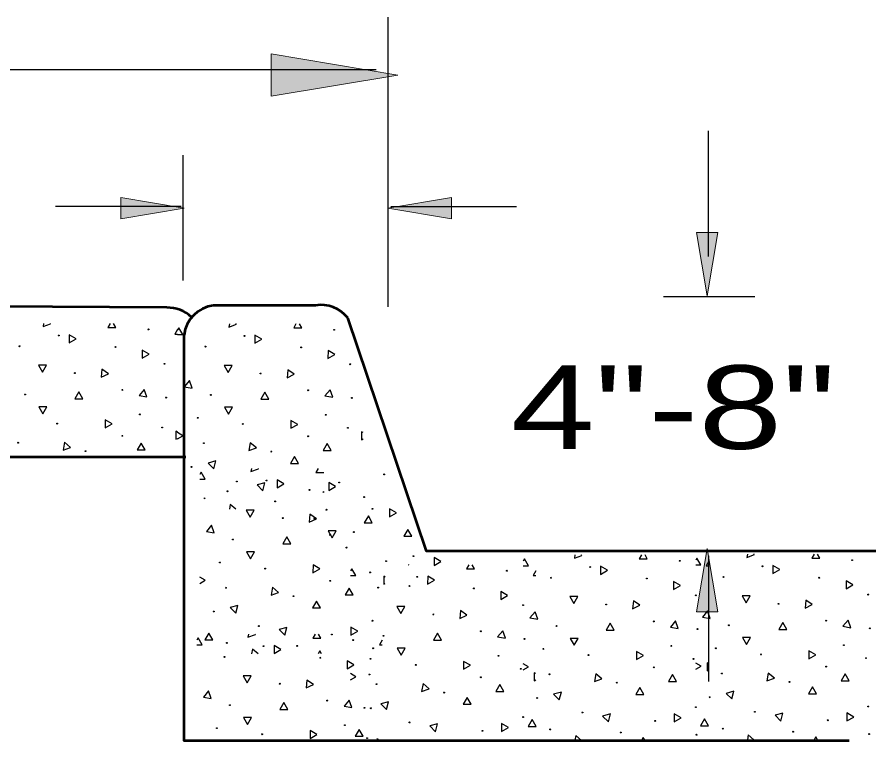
# Model space of a CAD drawing. Extents: x 75.6 to 110.9, y 28 to 50.
# Drawn here: x 101.892 to 103.142, y 35.919 to 36.973 of the extents above; entities that cross this region are included whole.
import ezdxf
from ezdxf.enums import TextEntityAlignment as Align

# ---------------------------------------------------------------- set-up
doc = ezdxf.new("R2010")
doc.units = 0
doc.header["$LTSCALE"] = 0.06
doc.layers.add('1', color=7, linetype='Continuous', lineweight=25)
doc.layers.add('3', color=7, linetype='Continuous', lineweight=13)

msp = doc.modelspace()

# ---------------------------------------------------------------- hatches: boundary and pattern name
at = {"layer": '3'}
for points in [[(102.26167, 36.9195), (102.26167, 36.85792), (102.44625, 36.88875), (102.44625, 36.88875)], [(102.04292, 36.6795), (102.04292, 36.71025), (102.13525, 36.69483), (102.13525, 36.69483)], [(102.52425, 36.6795), (102.52425, 36.71025), (102.43192, 36.69483), (102.43192, 36.69483)], [(102.912, 36.65958), (102.88125, 36.65958), (102.89667, 36.56733), (102.89667, 36.56733)], [(102.912, 36.10692), (102.88125, 36.10692), (102.89667, 36.19925), (102.89667, 36.19925)]]:
    msp.add_hatch(color=256, dxfattribs=at).paths.add_polyline_path(points)

# ---------------------------------------------------------------- linework, layer by layer
at = {"layer": '1', "lineweight": 53}
for p, q in [((102.10992, 36.55025), (98.82217, 36.57225)), ((102.32642, 36.55342), (102.17775, 36.55342)), ((102.13775, 36.33233), (98.82217, 36.33233))]:
    msp.add_line(p, q, dxfattribs=at)
at = {"layer": '1'}
for p, q in [((101.93058, 36.527), (101.92983, 36.52242)), ((101.92983, 36.52242), (101.94075, 36.52642)), ((101.94075, 36.52642), (101.94, 36.527)), ((102.02758, 36.527), (102.02425, 36.52125)), ((102.03592, 36.52125), (102.03258, 36.527)), ((102.201, 36.52642), (102.20025, 36.52183)), ((102.20025, 36.52183), (102.21117, 36.52583)), ((102.21117, 36.52583), (102.21042, 36.52642)), ((102.298, 36.52642), (102.29467, 36.52067)), ((102.30633, 36.52067), (102.303, 36.52642)), ((102.02425, 36.52125), (102.03592, 36.52125)), ((102.12533, 36.51817), (102.12142, 36.51133)), ((102.12767, 36.52083), (102.12575, 36.51758)), ((102.13342, 36.51075), (102.12767, 36.52083)), ((102.29467, 36.52067), (102.30633, 36.52067)), ((102.12142, 36.51133), (102.12533, 36.51133)), ((102.12575, 36.51075), (102.13342, 36.51075)), ((102.123, 36.37), (102.123, 36.35833)), ((102.123, 36.37), (102.123, 36.35833)), ((102.12533, 36.36867), (102.123, 36.37)), ((102.12533, 36.36867), (102.123, 36.37)), ((102.39342, 36.36942), (102.39342, 36.35775)), ((102.39342, 36.36942), (102.39342, 36.35775)), ((102.39575, 36.36808), (102.39342, 36.36942)), ((102.39575, 36.36808), (102.39342, 36.36942)), ((102.123, 36.35833), (102.12533, 36.35967)), ((102.123, 36.35833), (102.12533, 36.35967)), ((102.39342, 36.35775), (102.39575, 36.35908)), ((102.39342, 36.35775), (102.39575, 36.35908)), ((102.23325, 36.31583), (102.23242, 36.31125)), ((102.23242, 36.31125), (102.24342, 36.31525)), ((102.24342, 36.31525), (102.24275, 36.31583)), ((102.33025, 36.31583), (102.32692, 36.31008)), ((102.15992, 36.31025), (102.158, 36.307)), ((102.158, 36.30025), (102.16575, 36.30025)), ((102.16575, 36.30025), (102.15992, 36.31025)), ((102.32692, 36.31008), (102.3385, 36.31008)), ((102.70408, 36.18992), (102.70333, 36.18533)), ((102.70333, 36.18533), (102.71425, 36.18933)), ((102.71425, 36.18933), (102.7135, 36.18992)), ((102.80108, 36.18992), (102.79775, 36.18417)), ((102.80942, 36.18417), (102.80608, 36.18992)), ((102.95508, 36.19092), (102.95433, 36.18642)), ((102.95433, 36.18642), (102.96533, 36.19042)), ((102.96533, 36.19042), (102.96458, 36.19092)), ((103.05208, 36.19092), (103.04875, 36.18525)), ((103.06042, 36.18525), (103.05708, 36.19092)), ((102.46267, 36.17492), (102.46192, 36.1755)), ((102.5495, 36.1755), (102.54608, 36.16975)), ((102.55775, 36.16975), (102.55442, 36.1755)), ((102.63075, 36.18433), (102.62883, 36.18108)), ((102.62883, 36.17425), (102.6365, 36.17425)), ((102.6365, 36.17425), (102.63075, 36.18433)), ((102.79775, 36.18417), (102.80942, 36.18417)), ((102.88175, 36.18542), (102.87992, 36.18217)), ((102.87992, 36.17533), (102.88758, 36.17533)), ((102.88758, 36.17533), (102.88175, 36.18542)), ((102.89883, 36.18108), (102.89492, 36.17425)), ((102.89492, 36.17425), (102.89883, 36.17425)), ((103.04875, 36.18525), (103.06042, 36.18525)), ((102.37908, 36.16992), (102.37725, 36.16667)), ((102.38492, 36.15992), (102.37908, 36.16992)), ((102.54608, 36.16975), (102.55775, 36.16975)), ((102.64725, 36.16667), (102.64333, 36.15992)), ((102.37725, 36.15992), (102.38492, 36.15992)), ((102.42575, 36.15883), (102.42567, 36.14725)), ((102.42575, 36.15883), (102.42567, 36.14725)), ((102.428, 36.1575), (102.42575, 36.15883)), ((102.428, 36.1575), (102.42575, 36.15883)), ((102.64333, 36.15992), (102.64725, 36.15992)), ((102.42567, 36.14725), (102.428, 36.14858)), ((102.42567, 36.14725), (102.428, 36.14858)), ((102.22883, 36.07458), (102.22808, 36.07)), ((102.22808, 36.07), (102.239, 36.074)), ((102.239, 36.074), (102.23833, 36.07458)), ((102.32583, 36.07458), (102.3225, 36.06883)), ((102.33408, 36.06883), (102.33075, 36.07458)), ((102.1555, 36.069), (102.15358, 36.06575)), ((102.16133, 36.05892), (102.1555, 36.069)), ((102.3225, 36.06883), (102.33408, 36.06883)), ((102.42358, 36.06575), (102.41967, 36.05892)), ((102.15358, 36.05892), (102.16133, 36.05892)), ((102.41967, 36.05892), (102.42358, 36.05892)), ((102.8965, 36.03292), (102.8965, 36.02125)), ((102.8965, 36.03292), (102.8965, 36.02125)), ((102.89883, 36.03158), (102.8965, 36.03292)), ((102.89883, 36.03158), (102.8965, 36.03292)), ((102.64492, 36.0185), (102.64492, 36.00683)), ((102.64492, 36.0185), (102.64492, 36.00683)), ((102.64725, 36.01717), (102.64492, 36.0185)), ((102.64725, 36.01717), (102.64492, 36.0185)), ((102.8965, 36.02125), (102.89883, 36.02258)), ((102.8965, 36.02125), (102.89883, 36.02258)), ((102.64492, 36.00683), (102.64725, 36.00825)), ((102.64492, 36.00683), (102.64725, 36.00825))]:
    msp.add_line(p, q, dxfattribs=at)
at = {"layer": '1', "lineweight": 53}
for points in [[(103.14208, 36.19567), (102.48817, 36.19567), (102.37333, 36.53525)], [(103.10308, 35.91925), (102.13525, 35.91925), (102.13525, 36.51258)]]:
    msp.add_lwpolyline(points, dxfattribs=at)
at = {"layer": '1'}
for points in [[(101.96775, 36.49875), (101.97783, 36.50467), (101.96783, 36.5105)], [(102.23817, 36.49817), (102.24825, 36.50408), (102.23825, 36.50992)], [(102.07408, 36.4765), (102.08425, 36.48233), (102.07425, 36.48817)], [(102.3445, 36.47592), (102.35467, 36.48175), (102.34467, 36.48758)], [(101.92883, 36.45633), (101.93458, 36.46633), (101.923, 36.46633)], [(102.19925, 36.45575), (102.205, 36.46575), (102.19342, 36.46575)], [(102.0145, 36.44867), (102.025, 36.45367), (102.01558, 36.46033)], [(102.28492, 36.44808), (102.29542, 36.45308), (102.286, 36.45975)], [(102.13542, 36.43492), (102.14692, 36.43292), (102.143, 36.44375)], [(101.97625, 36.41742), (101.98783, 36.41742), (101.982, 36.4275)], [(102.06958, 36.42208), (102.08108, 36.42008), (102.07717, 36.431)], [(102.24667, 36.41683), (102.25825, 36.41683), (102.25242, 36.42692)], [(102.34, 36.4215), (102.3515, 36.4195), (102.34758, 36.43042)], [(101.92925, 36.39542), (101.93508, 36.4055), (101.92342, 36.4055)], [(102.19967, 36.39483), (102.2055, 36.40492), (102.19383, 36.40492)], [(102.02017, 36.37492), (102.03025, 36.38067), (102.02025, 36.3865)], [(102.29058, 36.37433), (102.30067, 36.38008), (102.29067, 36.38592)], [(101.959, 36.3425), (101.96992, 36.3465), (101.961, 36.354)], [(102.06692, 36.34283), (102.07858, 36.34283), (102.07275, 36.35292)], [(102.22942, 36.34192), (102.24033, 36.34592), (102.23142, 36.35342)], [(102.33733, 36.34225), (102.349, 36.34225), (102.34317, 36.35233)], [(102.17825, 36.31558), (102.18125, 36.32683), (102.17, 36.32383)], [(102.28983, 36.32333), (102.30142, 36.32333), (102.29567, 36.33342)], [(102.27042, 36.28758), (102.2805, 36.2935), (102.27042, 36.29933)], [(102.24967, 36.2835), (102.25267, 36.29483), (102.24133, 36.29183)], [(102.34567, 36.28358), (102.35567, 36.28942), (102.34567, 36.29525)], [(102.23142, 36.24517), (102.23733, 36.25525), (102.22567, 36.25525)], [(102.31708, 36.23758), (102.32775, 36.2425), (102.31817, 36.24917)], [(102.43425, 36.24558), (102.44433, 36.25142), (102.43433, 36.25725)], [(102.39742, 36.23683), (102.40908, 36.23683), (102.40333, 36.24692)], [(102.16775, 36.22433), (102.17908, 36.22233), (102.17517, 36.23325)], [(102.3505, 36.21483), (102.35633, 36.22492), (102.34475, 36.22492)], [(102.45492, 36.21708), (102.46658, 36.21708), (102.46075, 36.22717)], [(102.27883, 36.20625), (102.2905, 36.20625), (102.28475, 36.21633)], [(102.23192, 36.18425), (102.23775, 36.19442), (102.22608, 36.19442)], [(102.32275, 36.16375), (102.33292, 36.16958), (102.32283, 36.17542)], [(102.49892, 36.17458), (102.509, 36.18042), (102.49892, 36.18625)], [(102.99233, 36.16275), (103.00242, 36.16858), (102.99233, 36.17442)], [(102.74125, 36.16167), (102.75133, 36.16758), (102.74133, 36.17342)], [(102.48967, 36.14725), (102.49975, 36.15317), (102.48975, 36.159)], [(102.84758, 36.13942), (102.85775, 36.14525), (102.84775, 36.15108)], [(103.09867, 36.14042), (103.10875, 36.14625), (103.09875, 36.15217)], [(102.26167, 36.13142), (102.27258, 36.13542), (102.26375, 36.14283)], [(102.3695, 36.13167), (102.38117, 36.13167), (102.37542, 36.14175)], [(102.596, 36.125), (102.60608, 36.13083), (102.59608, 36.13667)], [(102.70233, 36.11925), (102.70808, 36.12925), (102.6965, 36.12925)], [(102.95333, 36.12025), (102.95917, 36.13033), (102.9475, 36.13033)], [(103.03908, 36.11267), (103.04958, 36.11758), (103.04008, 36.12425)], [(102.2105, 36.105), (102.2135, 36.11625), (102.20225, 36.11325)], [(102.32208, 36.11283), (102.33375, 36.11283), (102.32792, 36.12283)], [(102.45075, 36.10483), (102.4565, 36.11492), (102.44492, 36.11492)], [(102.788, 36.11158), (102.7985, 36.11658), (102.78908, 36.12325)], [(102.53642, 36.09725), (102.54692, 36.10217), (102.53742, 36.10883)], [(102.6385, 36.09842), (102.65, 36.09642), (102.64608, 36.10725)], [(102.88958, 36.09942), (102.90108, 36.09742), (102.89708, 36.10833)], [(102.74975, 36.08033), (102.76133, 36.08033), (102.7555, 36.09042)], [(102.84308, 36.085), (102.85458, 36.083), (102.85067, 36.09392)], [(103.00075, 36.08142), (103.01242, 36.08142), (103.00658, 36.09142)], [(103.09417, 36.086), (103.10567, 36.084), (103.10175, 36.095)], [(102.16508, 36.06625), (102.17675, 36.06625), (102.17092, 36.07625)], [(102.28183, 36.073), (102.28483, 36.08425), (102.27358, 36.08125)], [(102.37783, 36.073), (102.38792, 36.07883), (102.37792, 36.08467)], [(102.49808, 36.06592), (102.50975, 36.06592), (102.50392, 36.076)], [(102.5915, 36.07058), (102.603, 36.06858), (102.59908, 36.07958)], [(102.70275, 36.05833), (102.70858, 36.06842), (102.69692, 36.06842)], [(102.95375, 36.05942), (102.95967, 36.0695), (102.948, 36.0695)], [(102.266, 36.04633), (102.27608, 36.05225), (102.26608, 36.058)], [(102.45108, 36.04392), (102.457, 36.054), (102.44533, 36.054)], [(102.79367, 36.03783), (102.80375, 36.04358), (102.79375, 36.04942)], [(103.04475, 36.03883), (103.05475, 36.04467), (103.04475, 36.0505)], [(102.37233, 36.024), (102.38242, 36.02992), (102.37242, 36.03575)], [(102.54208, 36.02342), (102.55208, 36.02925), (102.54208, 36.035)], [(102.22708, 36.00383), (102.23292, 36.01392), (102.22125, 36.01392)], [(102.7325, 36.00542), (102.74342, 36.00942), (102.7345, 36.01692)], [(102.84042, 36.00575), (102.85208, 36.00575), (102.84625, 36.01583)], [(102.9835, 36.0065), (102.9945, 36.0105), (102.98558, 36.01792)], [(103.09142, 36.00683), (103.10308, 36.00683), (103.09733, 36.01683)], [(102.31275, 35.99625), (102.32333, 36.00125), (102.31375, 36.00783)], [(102.48092, 35.991), (102.49183, 35.995), (102.48292, 36.0025)], [(102.58875, 35.99133), (102.60042, 35.99133), (102.59467, 36.00142)], [(102.16333, 35.983), (102.17475, 35.981), (102.17075, 35.99192)], [(102.68133, 35.97908), (102.68433, 35.99033), (102.67308, 35.98733)], [(102.79292, 35.98683), (102.8045, 35.98683), (102.79875, 35.99692)], [(102.93242, 35.98017), (102.93542, 35.99142), (102.92408, 35.98842)], [(103.04392, 35.98792), (103.05558, 35.98792), (103.04975, 35.99792)], [(102.27442, 35.965), (102.28608, 35.965), (102.28033, 35.975)], [(102.36792, 35.96958), (102.37933, 35.96758), (102.37542, 35.97858)], [(102.42975, 35.96467), (102.43275, 35.97592), (102.4215, 35.97292)], [(102.54133, 35.97242), (102.55292, 35.97242), (102.54708, 35.9825)], [(102.2275, 35.943), (102.23333, 35.95308), (102.22175, 35.95308)], [(102.63592, 35.94025), (102.64758, 35.94025), (102.64175, 35.95033)], [(102.75275, 35.947), (102.75575, 35.95833), (102.74442, 35.95533)], [(102.84875, 35.94708), (102.85875, 35.95292), (102.84875, 35.95875)], [(102.887, 35.94133), (102.89867, 35.94133), (102.89283, 35.95142)], [(103.00375, 35.94808), (103.00675, 35.95942), (102.9955, 35.95642)], [(103.09975, 35.94817), (103.10983, 35.95392), (103.09975, 35.95983)], [(102.50108, 35.93258), (102.50408, 35.94392), (102.49283, 35.94092)], [(102.59708, 35.93267), (102.60717, 35.9385), (102.59708, 35.94433)], [(102.31842, 35.92242), (102.3285, 35.92825), (102.31842, 35.93408)], [(102.38433, 35.92592), (102.396, 35.92592), (102.39017, 35.93592)]]:
    msp.add_lwpolyline(points, close=True, dxfattribs=at)
for points in [[(102.12575, 36.35908), (102.1335, 36.36358), (102.12575, 36.36808)], [(102.21042, 36.25642), (102.20225, 36.26333), (102.201, 36.25642)], [(102.21042, 36.25642), (102.20225, 36.26333), (102.201, 36.25642)], [(102.158, 36.14858), (102.16575, 36.153), (102.158, 36.1575)], [(102.24275, 36.04583), (102.2345, 36.05275), (102.23325, 36.04583)], [(102.24275, 36.04583), (102.2345, 36.05275), (102.23325, 36.04583)], [(102.33517, 36.04583), (102.33275, 36.05017), (102.33025, 36.04583)], [(102.62883, 36.02258), (102.63658, 36.02708), (102.62883, 36.03158)], [(102.87992, 36.02358), (102.88767, 36.02817), (102.87992, 36.03258)], [(102.37725, 36.00825), (102.385, 36.01267), (102.37725, 36.01717)], [(102.7135, 35.91992), (102.70533, 35.92683), (102.70408, 35.91992)], [(102.7135, 35.91992), (102.70533, 35.92683), (102.70408, 35.91992)], [(102.80608, 35.91992), (102.80358, 35.92425), (102.80108, 35.91992)], [(102.96458, 35.92092), (102.95642, 35.92783), (102.95508, 35.92092)], [(102.96458, 35.92092), (102.95642, 35.92783), (102.95508, 35.92092)], [(103.05708, 35.92092), (103.05467, 35.92525), (103.05208, 35.92092)]]:
    msp.add_lwpolyline(points, dxfattribs=at)
for centre in [(102.08315, 36.51842), (102.35356, 36.51783), (101.95262, 36.50948), (102.22304, 36.5089), (101.89572, 36.49387), (102.03518, 36.49277), (102.16614, 36.49329), (102.30559, 36.49218), (102.10659, 36.46822), (102.37701, 36.46764), (101.97605, 36.45483), (102.24646, 36.45425), (101.90355, 36.42358), (102.04523, 36.43028), (102.31565, 36.4297), (102.10882, 36.41912), (102.17397, 36.423), (102.37923, 36.41854), (102.07088, 36.39458), (102.155, 36.38954), (102.3413, 36.39399), (101.9504, 36.38119), (102.10324, 36.37561), (102.22081, 36.38061), (102.37365, 36.37503), (102.04523, 36.36335), (102.31565, 36.36276), (101.89349, 36.35331), (102.16391, 36.35273), (101.99168, 36.34103), (102.2621, 36.34044), (102.14607, 36.31815), (102.25527, 36.29835), (102.4264, 36.3073), (102.21188, 36.29693), (102.36093, 36.2954), (102.19837, 36.28274), (102.31788, 36.28467), (102.33783, 36.28163), (102.3973, 36.27425), (102.16503, 36.2724), (102.26768, 36.26793), (102.34233, 36.25585), (102.40924, 36.25709), (102.2787, 36.2437), (102.3248, 36.243), (102.3823, 36.22325), (102.2062, 36.21245), (102.34788, 36.21915), (102.37165, 36.20061), (102.46897, 36.18824), (102.18723, 36.17899), (102.42915, 36.18086), (102.85665, 36.18133), (102.97717, 36.17345), (103.1077, 36.18238), (102.25305, 36.17006), (102.40589, 36.16448), (102.60505, 36.16693), (102.72612, 36.1724), (102.34788, 36.15221), (102.47452, 36.158), (102.66922, 36.15679), (102.80868, 36.15568), (102.92027, 36.15784), (103.05973, 36.15673), (102.19614, 36.14218), (102.41762, 36.14239), (102.46339, 36.14473), (102.55708, 36.14128), (102.29433, 36.12989), (102.88009, 36.13114), (103.13114, 36.13219), (102.62849, 36.11674), (102.74955, 36.11775), (103.0006, 36.1188), (102.1783, 36.1076), (102.49795, 36.10335), (102.24411, 36.08638), (102.40924, 36.09421), (102.67705, 36.0865), (102.81873, 36.0932), (102.9281, 36.08755), (103.06978, 36.09425), (102.35011, 36.07412), (102.56713, 36.0788), (102.88232, 36.08204), (103.13337, 36.08309), (102.19727, 36.06185), (102.3814, 36.06598), (102.42545, 36.0721), (102.63072, 36.06764), (102.25087, 36.05705), (102.29991, 36.05738), (102.41034, 36.05405), (102.65808, 36.05304), (102.84438, 36.05749), (102.90913, 36.05409), (103.09543, 36.05854), (102.19397, 36.04144), (102.33343, 36.04033), (102.40648, 36.03864), (102.59278, 36.04309), (102.7239, 36.04411), (102.87674, 36.03853), (102.97495, 36.04516), (103.12779, 36.03958), (102.4723, 36.02971), (102.62514, 36.02413), (102.81873, 36.02626), (103.06978, 36.02731), (102.40484, 36.01579), (102.56713, 36.01186), (102.66699, 36.01623), (102.91804, 36.01728), (102.2743, 36.0024), (102.41539, 36.00183), (102.76518, 36.00394), (103.01623, 36.00499), (102.51358, 35.98954), (102.34348, 35.97785), (102.64915, 35.98165), (102.9002, 35.9827), (102.2018, 35.97115), (102.39755, 35.96725), (102.40707, 35.96669), (102.88009, 35.96826), (102.96601, 35.96148), (103.13114, 35.96931), (102.62849, 35.95386), (102.71496, 35.96043), (103.07201, 35.94922), (102.18283, 35.93769), (102.36913, 35.94214), (102.46336, 35.94603), (102.66812, 35.9359), (102.82096, 35.94817), (102.91917, 35.93695), (102.24865, 35.92876), (102.56936, 35.93377), (102.77076, 35.93143), (102.88119, 35.9281), (103.02181, 35.93248), (103.13224, 35.92915), (102.40149, 35.92318), (102.41652, 35.9215)]:
    msp.add_circle(centre, 0.000647, dxfattribs=at)
at = {"layer": '1', "lineweight": 53}
for centre, start, end in [((102.11108, 36.50018), 46.22964, 91.33763), ((102.18453, 36.50383), 97.74425, 172.25575), ((102.33428, 36.50398), 38.74942, 99.04688)]:
    msp.add_arc(centre, 0.05, start, end, dxfattribs=at)
at = {"layer": '3', "lineweight": 25}
for p, q in [((102.43233, 36.55108), (102.43233, 36.97308)), ((102.41458, 36.89625), (98.84517, 36.89625)), ((102.89842, 36.62467), (102.89842, 36.8075)), ((102.13383, 36.58942), (102.13383, 36.77225)), ((102.13092, 36.69725), (101.94808, 36.69725)), ((102.43625, 36.69725), (102.61908, 36.69725)), ((102.96592, 36.56558), (102.83292, 36.56558)), ((102.89842, 36.18842), (102.89842, 36.00558))]:
    msp.add_line(p, q, dxfattribs=at)
at = {"layer": '3'}
for points in [[(102.26167, 36.9195), (102.26167, 36.85792), (102.44625, 36.88875), (102.44625, 36.88875)], [(102.04292, 36.6795), (102.04292, 36.71025), (102.13525, 36.69483), (102.13525, 36.69483)], [(102.52425, 36.6795), (102.52425, 36.71025), (102.43192, 36.69483), (102.43192, 36.69483)], [(102.912, 36.65958), (102.88125, 36.65958), (102.89667, 36.56733), (102.89667, 36.56733)], [(102.912, 36.10692), (102.88125, 36.10692), (102.89667, 36.19925), (102.89667, 36.19925)]]:
    msp.add_lwpolyline(points, close=True, dxfattribs=at)

# ---------------------------------------------------------------- texts
at = {"layer": '1', "width": 1.35}
msp.add_text('4"-8"', height=0.1215, dxfattribs=at).set_placement((102.84729, 36.34442), align=Align.CENTER)

doc.saveas('drawing.dxf')
